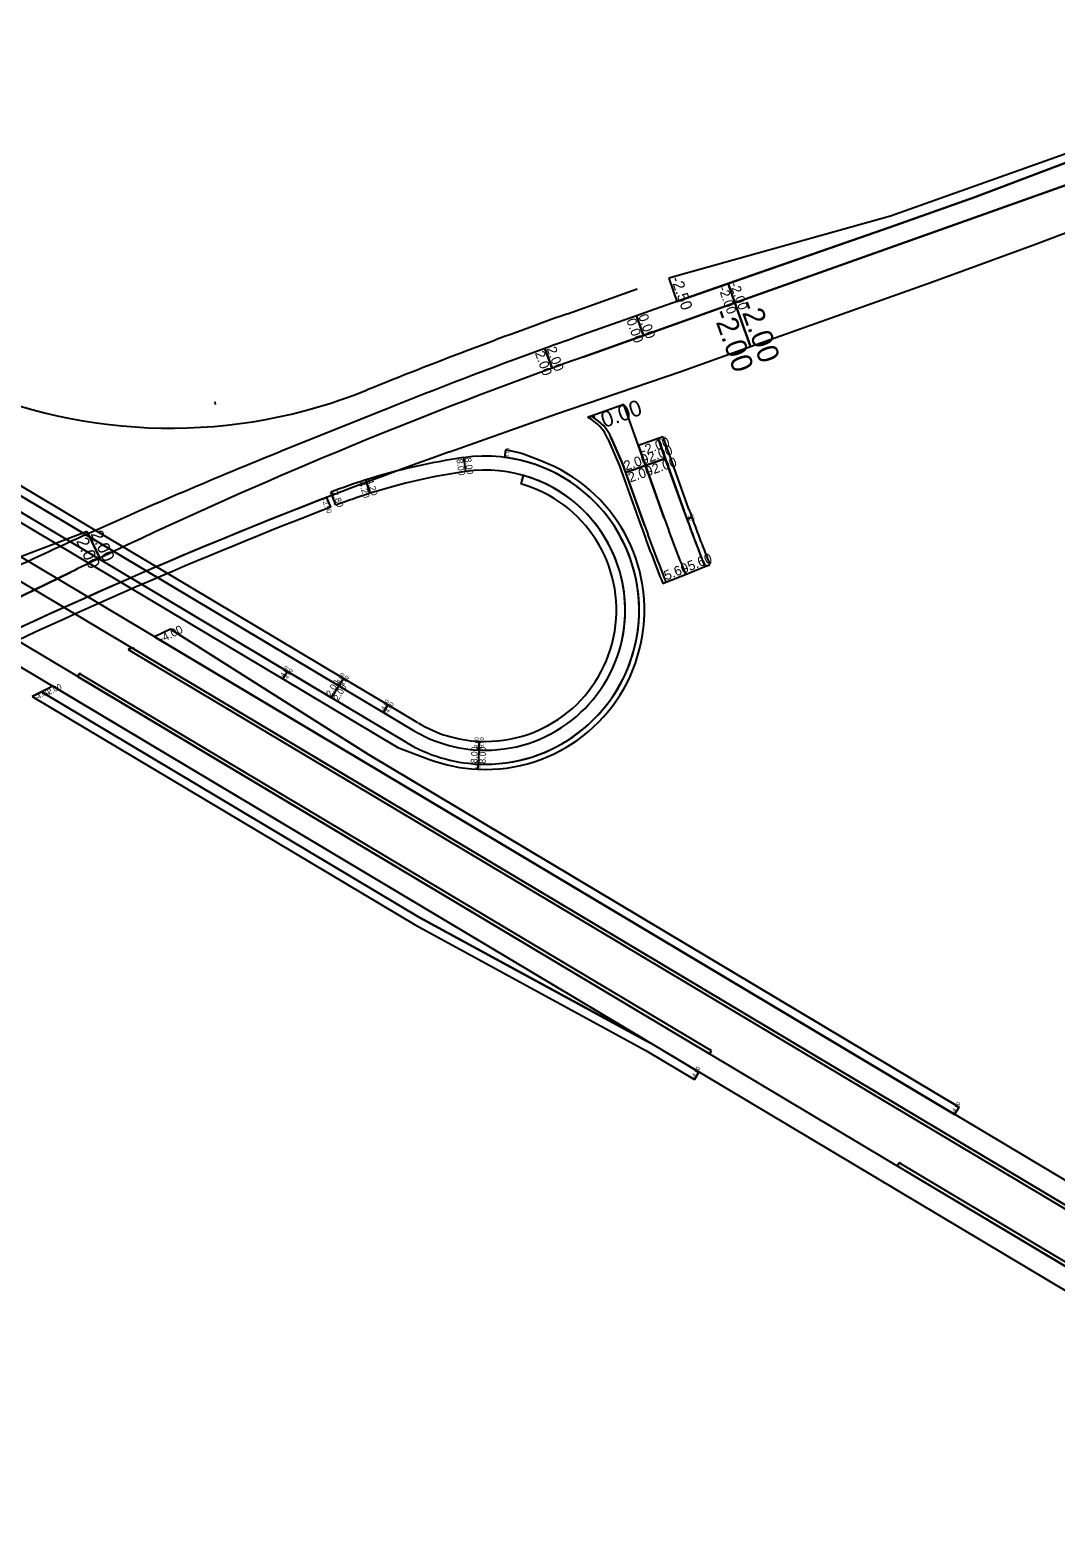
# Model space of a CAD drawing. Extents: x 2342222 to 2351711, y 366548 to 372860.
# Drawn here: x 2349395 to 2350568, y 366977 to 368699 of the extents above; entities that cross this region are included whole.
import ezdxf

# ---------------------------------------------------------------- set-up
doc = ezdxf.new("R2010")
doc.units = 0
for name, color, linetype in [('RD_HC_Cl', 7, 'Continuous'), ('RD_PD_PaveShd', 7, 'Continuous'), ('RD_PD_SuperShp_BL_EB_526', 7, 'Continuous'), ('RD_PD_SuperShp_BL_WB_526', 7, 'Continuous'), ('RD_PD_SuperShp_Rel_LINE-1', 7, 'Continuous'), ('RD_PD_SuperShp_Rel_LINE-2', 7, 'Continuous'), ('RD_PD_SuperShp_Rel_Line-4', 7, 'Continuous'), ('RD_PD_SuperShp_S-97', 7, 'Continuous')]:
    doc.layers.add(name, color=color, linetype=linetype)

msp = doc.modelspace()

# ---------------------------------------------------------------- linework, layer by layer
at = {"layer": 'RD_HC_Cl'}
msp.add_line((2350009.4, 368375.2), (2350089.1, 368403.6), dxfattribs=at)
msp.add_line((2350009.4, 368375.2), (2350089.1, 368403.6), dxfattribs=at)
for centre, radius, start, end in [((2351947.8, 362927.7), 5782.1, 109.58804, 112.01473), ((2351947.8, 362927.7), 5782.1, 109.58804, 112.01473), ((2349555.5, 368844.5), 600, 245.9774, 292.0147), ((2349555.5, 368844.5), 600, 245.9774, 292.0147)]:
    msp.add_arc(centre, radius, start, end, dxfattribs=at)
at = {"layer": 'RD_PD_PaveShd'}
for p, q in [((2349555.3, 368014.9), (2349537, 368006)), ((2349555.3, 368014.9), (2349782, 367871.5)), ((2349506.9, 367991.4), (2351125.7, 367025.5)), ((2349397.4, 367937.9), (2349835.2, 367676.8)), ((2349835.2, 367676.8), (2350098.9, 367533.4)), ((2350098.9, 367533.4), (2350154.4, 367500.2)), ((2350159.6, 367508.8), (2350154.4, 367500.2))]:
    msp.add_line(p, q, dxfattribs=at)
at = {"layer": 'RD_PD_SuperShp_BL_EB_526'}
for p, q in [((2348584, 368476.8), (2351064, 366997.1)), ((2351051.7, 366976.5), (2348571.6, 368456.3)), ((2349451, 367964.2), (2349449, 367960.7)), ((2349449, 367960.7), (2350171.8, 367529.5)), ((2350173.8, 367532.9), (2349451, 367964.2)), ((2349421, 367949.5), (2349408.1, 367943.2)), ((2350100, 367544.4), (2349421, 367949.5)), ((2349397.4, 367937.9), (2349408.1, 367943.2)), ((2349408.1, 367943.2), (2349397.4, 367937.9)), ((2349397.4, 367937.9), (2349835.2, 367676.8)), ((2349408.1, 367943.2), (2349840.1, 367685.4)), ((2349408.1, 367943.2), (2349840.1, 367685.4)), ((2349840.1, 367685.4), (2349408.1, 367943.2)), ((2349840.1, 367685.4), (2350103.9, 367542)), ((2349840.1, 367685.4), (2350099.9, 367544.2)), ((2350103.9, 367542), (2349840.1, 367685.4)), ((2349835.2, 367676.8), (2350098.9, 367533.4)), ((2350098.9, 367533.4), (2350154.4, 367500.2)), ((2350099.9, 367544.2), (2350100, 367544.4)), ((2350159.6, 367508.8), (2350103.9, 367542)), ((2350171.8, 367529.5), (2350173.8, 367532.9)), ((2350154.4, 367500.2), (2350159.6, 367508.8)), ((2350388.4, 367404.9), (2350386.3, 367401.5)), ((2350386.3, 367401.5), (2351002.2, 367034)), ((2351004.3, 367037.5), (2350388.4, 367404.9))]:
    msp.add_line(p, q, dxfattribs=at)
at = {"layer": 'RD_PD_SuperShp_BL_WB_526'}
for p, q in [((2350982.8, 367143.5), (2348626.9, 368549)), ((2348614.8, 368528.3), (2350970.5, 367122.8)), ((2349555.3, 368014.9), (2349537, 368006)), ((2349782, 367871.5), (2349555.3, 368014.9)), ((2349537, 368006), (2350451.8, 367460.2)), ((2349511.2, 367993.5), (2349506.9, 367991.4)), ((2349506.9, 367991.4), (2350968.4, 367119.4)), ((2350970.5, 367122.8), (2349511.2, 367993.5)), ((2349782, 367871.5), (2350457, 367468.8)), ((2350457, 367468.8), (2349782, 367871.5)), ((2350451.8, 367460.2), (2350457, 367468.8)), ((2350451.8, 367460.2), (2350457, 367468.8))]:
    msp.add_line(p, q, dxfattribs=at)
at = {"layer": 'RD_PD_SuperShp_Rel_LINE-1'}
for p, q in [((2350073.7, 368271.5), (2350036.3, 368258.2)), ((2350098.4, 368202), (2350073.7, 368271.5)), ((2350038.3, 368257.1), (2350040.5, 368258)), ((2350040.5, 368258), (2350038.3, 368257.1)), ((2350040.5, 368258), (2350040.5, 368258)), ((2350059.3, 368233.6), (2350072.6, 368202.9)), ((2350112.9, 368232.8), (2350090.3, 368224.7)), ((2350090.3, 368224.7), (2350098.4, 368202)), ((2350118.6, 368234.6), (2350112.9, 368232.8)), ((2350121, 368210), (2350112.9, 368232.8)), ((2350112.9, 368232.8), (2350142.5, 368149.8)), ((2350148.1, 368151.8), (2350118.6, 368234.6)), ((2350072.6, 368202.9), (2350075.8, 368193.9)), ((2350075.8, 368193.9), (2350098.4, 368202)), ((2350098.4, 368202), (2350075.8, 368193.9)), ((2350098.4, 368202), (2350121, 368210)), ((2350121, 368210), (2350098.4, 368202)), ((2350098.4, 368202), (2350119.9, 368141.7)), ((2350119.9, 368141.7), (2350098.4, 368202)), ((2350142.5, 368149.8), (2350121, 368210)), ((2350075.8, 368193.9), (2350097.2, 368133.7)), ((2350151.4, 368142.7), (2350145.7, 368140.6)), ((2350145.7, 368140.6), (2350151.4, 368142.7)), ((2350144.2, 368077.3), (2350166.5, 368086.3)), ((2350166.5, 368086.3), (2350172, 368088.5)), ((2350121.9, 368068.4), (2350144.2, 368077.3))]:
    msp.add_line(p, q, dxfattribs=at)
for centre, radius, start, end in [((2350013.4, 368213.7), 50, 60.1779, 62.8004), ((2350013.4, 368213.7), 50, 23.4033, 60.1779), ((2351779.9, 368732.5), 1732, 199.588, 199.9082), ((2351779.9, 368732.5), 1786, 199.588, 201.8268), ((2351779.9, 368732.5), 1762, 199.588, 201.8268), ((2351779.9, 368732.5), 1762, 199.588, 201.8268), ((2351779.9, 368732.5), 1738, 199.588, 201.8268), ((2351779.9, 368732.5), 1738, 199.588, 199.9082), ((2351779.9, 368732.5), 1738, 199.9082, 201.8268), ((2351779.9, 368732.5), 1732, 199.9082, 201.8268)]:
    msp.add_arc(centre, radius, start, end, dxfattribs=at)
at = {"layer": 'RD_PD_SuperShp_Rel_LINE-2'}
msp.add_line((2349606.2, 368274.4), (2349606.4, 368271.4), dxfattribs=at)
at = {"layer": 'RD_PD_SuperShp_Rel_Line-4'}
for p, q in [((2350036.3, 368258.2), (2350032.5, 368256.9)), ((2349938.4, 368219.8), (2349937.3, 368211.1)), ((2350055.6, 368232.2), (2350068.9, 368201.5)), ((2350072.6, 368202.9), (2350059.3, 368233.6)), ((2349753.1, 367958.6), (2349333.9, 368208.7)), ((2349890.6, 368210.8), (2349892.8, 368194.9)), ((2349890.6, 368210.8), (2349892.8, 368194.9)), ((2350097.2, 368133.7), (2350072.6, 368202.9)), ((2349320.6, 368186.4), (2349739.7, 367936.3)), ((2349689.1, 367966.5), (2349320.6, 368186.4)), ((2349320.6, 368186.4), (2349739.7, 367936.3)), ((2349328.8, 368200.1), (2349747.9, 367950)), ((2349747.9, 367950), (2349328.8, 368200.1)), ((2349328.8, 368200.1), (2349747.9, 367950)), ((2349783.4, 368170.1), (2349778.6, 368185.3)), ((2349778.6, 368185.3), (2349783.4, 368170.1)), ((2349957.1, 368184.7), (2349956, 368180.9)), ((2349958.8, 368190.5), (2349957.1, 368184.7)), ((2350068.9, 368201.5), (2350093.5, 368132.3)), ((2349315.5, 368177.8), (2349683.9, 367957.9)), ((2349744.3, 368156.4), (2349738.6, 368171.3)), ((2350118.2, 368066.9), (2350121.9, 368068.4)), ((2349683.9, 367957.9), (2349689.1, 367966.5)), ((2349689.1, 367966.5), (2349683.9, 367957.9)), ((2349825.1, 367885.4), (2349689.1, 367966.5)), ((2349683.9, 367957.9), (2349815.4, 367879.5)), ((2349739.7, 367936.3), (2349747.9, 367950)), ((2349739.7, 367936.3), (2349747.9, 367950)), ((2349747.9, 367950), (2349753.1, 367958.6)), ((2349753.1, 367958.6), (2349747.9, 367950)), ((2349747.9, 367950), (2349833.3, 367899.1)), ((2349747.9, 367950), (2349799, 367919.6)), ((2349804.1, 367928.2), (2349753.1, 367958.6)), ((2349825.1, 367885.4), (2349739.7, 367936.3)), ((2349799, 367919.6), (2349804.1, 367928.2)), ((2349804.1, 367928.2), (2349799, 367919.6)), ((2349838.4, 367907.7), (2349804.1, 367928.2)), ((2349799, 367919.6), (2349833.3, 367899.1)), ((2349815.4, 367879.5), (2349851.7, 367866)), ((2349907.8, 367876.7), (2349907.1, 367860.7)), ((2349907.8, 367876.7), (2349907.1, 367860.7)), ((2349907.8, 367876.7), (2349908.3, 367886.7)), ((2349908.3, 367886.7), (2349907.8, 367876.7)), ((2349906.8, 367854.7), (2349907.1, 367860.7)), ((2349907.1, 367860.7), (2349906.8, 367854.7))]:
    msp.add_line(p, q, dxfattribs=at)
for centre, radius, start, end in [((2350009.7, 368212.4), 50, 23.4033, 62.8004), ((2350013.4, 368213.7), 50, 60.1779, 62.8004), ((2350013.4, 368213.7), 50, 23.4033, 60.1779), ((2349903.4, 368038.8), 184.4, 65.8479, 79.0662), ((2349988.4, 367521.7), 696, 98.078, 107.5407), ((2349915.3, 368036.5), 176, 348.6282, 98.0766), ((2349915.3, 368036.5), 176, 98.0766, 98.078), ((2349915.3, 368036.5), 182, 267.321, 69.5438), ((2349915.3, 368036.5), 176, 348.6282, 82.8073), ((2349988.4, 367521.7), 696, 107.5407, 111.0316), ((2349988.4, 367521.7), 680, 98.078, 107.5407), ((2349915.3, 368036.5), 160, 348.6282, 98.0766), ((2349915.3, 368036.5), 160, 98.0766, 98.078), ((2349915.3, 368036.5), 160, 21.9187, 74.238), ((2349988.4, 367521.7), 680, 107.5407, 111.0316), ((2349915.3, 368036.5), 150, 267.321, 74.2365), ((2351779.9, 368732.5), 1786, 199.588, 201.8268), ((2351779.9, 368732.5), 1790, 199.588, 201.8268), ((2349915.3, 368036.5), 160, 348.6282, 21.9187), ((2349915.3, 368036.5), 176, 267.321, 348.6282), ((2349915.3, 368036.5), 176, 267.321, 347.1065), ((2349915.3, 368036.5), 160, 267.321, 348.6282), ((2349915.3, 368036.5), 160, 267.321, 348.6282), ((2349915.3, 368036.5), 176, 347.1065, 348.6282), ((2349915.3, 368036.5), 160, 239.1785, 267.321), ((2349915.3, 368036.5), 160, 239.1785, 267.321), ((2349915.3, 368036.5), 150, 239.1785, 267.321), ((2349915.3, 368036.5), 176, 239.1785, 267.321), ((2349915.3, 368036.5), 176, 239.1785, 267.321), ((2349915.3, 368036.5), 182, 249.5465, 267.321)]:
    msp.add_arc(centre, radius, start, end, dxfattribs=at)
at = {"layer": 'RD_PD_SuperShp_S-97'}
for p, q in [((2350976.1, 368699.3), (2350378.4, 368486.7)), ((2350976.3, 368698.8), (2350475, 368508.5)), ((2350475, 368508.5), (2350976.3, 368698.8)), ((2350987.4, 368667.5), (2350200.8, 368387.6)), ((2350200.8, 368387.6), (2350987.4, 368667.5)), ((2350544.5, 368454.7), (2351001.5, 368628.1)), ((2350475, 368508.5), (2350378.1, 368474)), ((2350378.1, 368474), (2350475, 368508.5)), ((2350378.4, 368486.7), (2350125, 368415.9)), ((2350134.4, 368389.3), (2350378.1, 368474)), ((2350378.1, 368474), (2350193, 368409.6)), ((2350426.5, 368411.7), (2350544.5, 368454.7)), ((2350193, 368409.6), (2350108.5, 368380.2)), ((2350125, 368415.9), (2350134.4, 368389.3)), ((2350200.8, 368387.6), (2350193, 368409.6)), ((2350193, 368409.6), (2350200.8, 368387.6)), ((2350218.6, 368337.7), (2350426.5, 368411.7)), ((2350200.8, 368387.6), (2350027, 368325.7)), ((2350108.5, 368380.2), (2350088.2, 368373)), ((2350096.2, 368350.4), (2350200.8, 368387.6)), ((2350218.6, 368337.7), (2350200.8, 368387.6)), ((2350200.8, 368387.6), (2350218.6, 368337.7)), ((2350088.2, 368373), (2350018.9, 368348.3)), ((2350096.2, 368350.4), (2350088.2, 368373)), ((2350088.2, 368373), (2350096.2, 368350.4)), ((2350027, 368325.7), (2350096.2, 368350.4)), ((2349991.7, 368313.1), (2349983.5, 368335.6)), ((2349983.5, 368335.6), (2349991.7, 368313.1)), ((2350138.8, 368309.3), (2350218.6, 368337.7)), ((2349996.7, 368260.8), (2350138.8, 368309.3)), ((2349800.3, 368265.5), (2349681.4, 368217.7)), ((2349874.5, 368217.4), (2349996.7, 368260.8)), ((2349738.7, 368154.2), (2349734.1, 368165.3)), ((2349460.1, 368126.5), (2349355.7, 368086.8)), ((2349461.4, 368123.8), (2349460.1, 368126.5)), ((2349474.6, 368096), (2349461.4, 368123.8)), ((2349461.4, 368123.8), (2349474.6, 368096)), ((2349441.5, 368080), (2348933.2, 367832.8)), ((2349374.8, 368047.6), (2349441.5, 368080))]:
    msp.add_line(p, q, dxfattribs=at)
for centre, radius, start, end in [((2351947.8, 362927.7), 5753.6, 109.58804, 109.96253), ((2351947.8, 362927.7), 5753.6, 109.96253, 111.91571), ((2351947.8, 362927.7), 5729.6, 109.58804, 109.96253), ((2351947.8, 362927.7), 5729.6, 109.58804, 109.96253), ((2351947.8, 362927.7), 5729.6, 109.96253, 115.57252), ((2351947.8, 362927.7), 5729.6, 109.96253, 115.57252), ((2351783.3, 362853.3), 5693.6, 109.588, 115.9407), ((2351828.9, 362879.9), 5753.6, 111.91571, 114.29817), ((2351783.3, 362853.3), 5693.6, 111.0959, 115.9407), ((2351783.3, 362853.3), 5681.6, 111.0921, 115.9407), ((2351828.9, 362879.9), 5753.6, 114.29817, 115.40572), ((2351828.9, 362879.9), 5753.6, 114.29817, 115.40572), ((2351947.8, 362927.7), 5729.6, 115.57252, 115.94073), ((2351947.8, 362927.7), 5729.6, 115.57252, 115.94073)]:
    msp.add_arc(centre, radius, start, end, dxfattribs=at)

# ---------------------------------------------------------------- texts
at = {"layer": 'RD_PD_SuperShp_BL_EB_526'}
for height, rotation, p in [(1.84, 59.1902, (2349450.9, 367959.8)), (6.59, 26.0742, (2349413.8, 367938.3)), (0.0842, 59.1785, (2350099.9, 367544.2)), (1.84, 59.1785, (2350171.6, 367529.8)), (1.84, 59.1785, (2350388.2, 367400.5))]:
    msp.add_text('-2.00', height=height, rotation=rotation, dxfattribs=at).set_placement(p)
at = {"layer": 'RD_PD_SuperShp_BL_WB_526'}
for s, height, rotation, p in [('-4.00', 9.34, 25.9505, (2349545, 367999)), ('-2.00', 2.2, 25.9505, (2349508.8, 367989.7)), ('-4.00', 5.49, 26.0742, (2349402.1, 367933.8)), ('-4.00', 4.6, 59.1785, (2350154, 367500.9)), ('-4.00', 4.6, 59.1785, (2350451.4, 367460.9))]:
    msp.add_text(s, height=height, rotation=rotation, dxfattribs=at).set_placement(p)
at = {"layer": 'RD_PD_SuperShp_Rel_LINE-1'}
for s, height, rotation, p in [('0.00', 18.25, 19.588, (2350051.4, 368244.6)), ('-4.00', 1.84, 19.588, (2350034.1, 368255.5)), ('-2.00', 11.04, 19.588, (2350095.5, 368213.1)), ('-2.00', 11.04, 19.588, (2350098.8, 368203.9)), ('-4.00', 2.76, 18.1964, (2350114.2, 368229.8)), ('2.00', 11.04, 19.588, (2350076.1, 368195.8)), ('-2.00', 11.04, 19.588, (2350103.6, 368190.3)), ('2.00', 11.04, 19.588, (2350081, 368182.3)), ('-4.00', 2.76, 19.9082, (2350145.8, 368141.1)), ('-4.00', 2.76, 19.9082, (2350147.1, 368137.7)), ('-5.60', 11.04, 21.8268, (2350144.5, 368079.3)), ('5.60', 11.04, 21.8268, (2350122.2, 368070.3)), ('-5.60', 2.76, 21.8268, (2350166.5, 368086.7)), ('5.60', 1.84, 21.8268, (2350118.2, 368067.2))]:
    msp.add_text(s, height=height, rotation=rotation, dxfattribs=at).set_placement(p)
at = {"layer": 'RD_PD_SuperShp_Rel_Line-4'}
for s, height, rotation, p in [('8.00', 4.03, 82.8073, (2349942, 368210.9)), ('8.00', 7.36, 278.0766, (2349882.3, 368208.9)), ('8.00', 7.36, 278.0766, (2349891.8, 368210.3)), ('4.20', 7.36, 287.5407, (2349779.9, 368185)), ('2.80', 7.36, 291.0316, (2349739.9, 368171.1)), ('4.20', 7.36, 287.5407, (2349770.7, 368182.1)), ('-4.00', 4.6, 59.1785, (2349683.6, 367958.7)), ('-4.00', 4.6, 59.1785, (2349688.7, 367955.6)), ('-4.00', 4.6, 59.1785, (2349747.5, 367950.7)), ('-4.00', 4.6, 59.1785, (2349752.7, 367947.7)), ('2.00', 7.36, 59.1785, (2349739.1, 367937.4)), ('2.00', 7.36, 59.1785, (2349747.4, 367932.5)), ('-4.00', 4.6, 59.1785, (2349798.6, 367920.3)), ('8.00', 7.36, 87.321, (2349906, 367861.4)), ('8.00', 7.36, 87.321, (2349915.6, 367861)), ('8.00', 2.76, 87.321, (2349906.4, 367855)), ('8.00', 2.76, 87.321, (2349910, 367854.8))]:
    msp.add_text(s, height=height, rotation=rotation, dxfattribs=at).set_placement(p)
at = {"layer": 'RD_PD_SuperShp_S-97'}
for s, height, rotation, p in [('-2.50', 13, 289.588, (2350127.2, 368415.4)), ('-2.00', 10.75, 289.588, (2350194.8, 368409.3)), ('-2.00', 10.75, 289.588, (2350181.6, 368404.6)), ('0.00', 11.04, 289.588, (2350090.1, 368372.7)), ('-2.00', 24.38, 289.588, (2350175.1, 368376.2)), ('-2.00', 24.38, 289.588, (2350205, 368386.9)), ('0.00', 11.04, 289.588, (2350076.5, 368367.8)), ('2.00', 11.04, 289.9625, (2349971.9, 368330.4)), ('2.00', 11.04, 289.9625, (2349985.4, 368335.3)), ('-8.00', 2.76, 74.2758, (2349958, 368182.8)), ('-2.50', 5.52, 292.9125, (2349728.3, 368162.5)), ('2.00', 14.15, 295.5725, (2349447.2, 368115.6)), ('2.00', 1.38, 295.5725, (2349458.7, 368125.7)), ('2.00', 14.15, 295.5725, (2349463.8, 368123.6)), ('-4.00', 4.6, 59.1785, (2349803.7, 367917.2)), ('-8.00', 4.6, 87.321, (2349907.1, 367877.1)), ('-8.00', 4.6, 87.321, (2349913.1, 367876.8))]:
    msp.add_text(s, height=height, rotation=rotation, dxfattribs=at).set_placement(p)

doc.saveas('drawing.dxf')
